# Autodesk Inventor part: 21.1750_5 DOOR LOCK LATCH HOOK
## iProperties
Created: 2007-03
Part Number: 21.1750_5 DOOR LOCK LATCH HOOK
Material: Steel
Document SubType Name: Modeling
Designer: Andy Moles
Density: 7.85 g/cm^3
Author: Andy Moles
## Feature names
1. Base1
